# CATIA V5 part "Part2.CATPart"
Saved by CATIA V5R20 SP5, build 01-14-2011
Part number: Part2
Material "DS Black": density 7860 kg/m3, Young's modulus 2e+11 Pa, Poisson ratio 0.266
Bounding box of the stored display mesh (mm): x -20 to 20, y -12.5 to 12.5, z -60 to -47
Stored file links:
  D:\zhonggao\Part2.CATPart
  C:\Program Files\Dassault Systemes\B20\intel_a\startup\materials\Catalog.CATMaterial
  C:\Program Files\Dassault Systemes\B20\intel_a\startup\materials\black_env_512x512.jpg
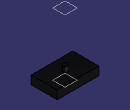
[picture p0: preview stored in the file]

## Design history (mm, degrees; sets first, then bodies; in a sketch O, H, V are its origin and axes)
Body1 (main body), material "DS Black"
  Set1
    Plane1: type Offset, RefPlane xy-plane, Offset 60, reversed
    Sketch1 on Plane1, origin (0, 0, -60), H (1, 0, 0), V (0, 1, 0)
      line L1 (20, 12.5) -> (20, -12.5)
      line L2 (20, -12.5) -> (-20, -12.5)
      line L3 (-20, -12.5) -> (-20, 12.5)
      line L4 (-20, 12.5) -> (20, 12.5)
      length L4 = 40
      length L1 = 25
      vertical: L1 V, L3 V
      horizontal: L2 H, L4 H
      equidistance: L1 L3 O, L2 L4 O
  Pad1: profile Sketch1, direction (0, 0, 1), length 8
  Sketch2 on end face of Pad1, origin (0, 0, -52), H (1, 0, 0), V (0, 1, 0)
    circle A1 centre (0, 0) radius 2.5
    radius A1 = 2.5
  Pad2: profile Sketch2, direction (0, 0, 1), length 5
